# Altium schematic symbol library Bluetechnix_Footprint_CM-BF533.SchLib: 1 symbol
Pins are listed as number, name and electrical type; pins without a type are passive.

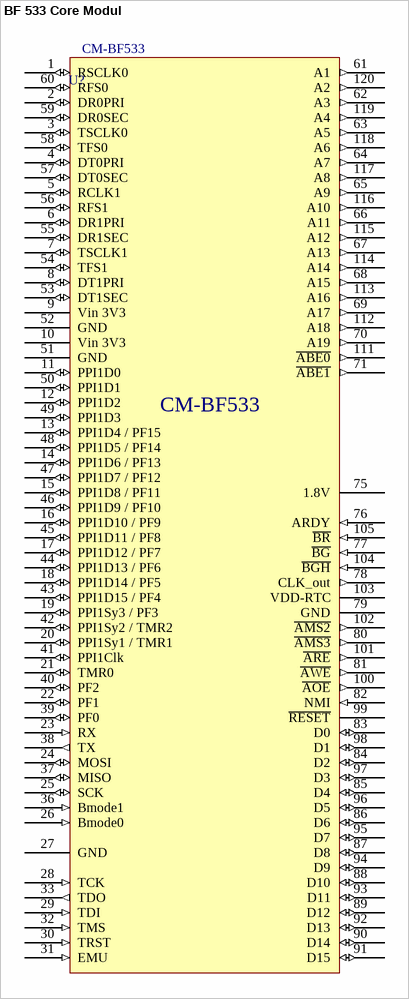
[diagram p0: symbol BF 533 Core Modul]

## BF 533 Core Modul
designator U?, comment CM-BF533
DSP Balckfin 533
pins: 1 RSCLK0 (io), 2 DR0PRI (io), 3 TSCLK0 (io), 4 DT0PRI (io), 5 RCLK1 (io), 6 DR1PRI (io), 7 TSCLK1 (io), 8 DT1PRI (io), 9 Vin 3V3 (power), 10 Vin 3V3 (power), 11 PPI1D0 (io), 12 PPI1D2 (io), 13 PPI1D4 / PF15 (io), 14 PPI1D6 / PF13 (io), 15 PPI1D8 / PF11 (io), 16 PPI1D10 / PF9 (io), 17 PPI1D12 / PF7 (io), 18 PPI1D14 / PF5 (io), 19 PPI1Sy3 / PF3 (io), 20 PPI1Sy1 / TMR1 (io), 21 TMR0 (io), 22 PF1 (io), 23 RX (in), 24 MOSI (io), 25 SCK (io), 26 Bmode0 (in), 27 GND (power), 28 TCK (in), 29 TDI (in), 30 TRST (in), 31 EMU (in), 32 TMS (in), 33 TDO (out), 36 Bmode1 (in), 37 MISO (io), 38 TX (out), 39 PF0 (io), 40 PF2 (io), 41 PPI1Clk (io), 42 PPI1Sy2 / TMR2 (io), 43 PPI1D15 / PF4 (io), 44 PPI1D13 / PF6 (io), 45 PPI1D11 / PF8 (io), 46 PPI1D9 / PF10 (io), 47 PPI1D7 / PF12 (io), 48 PPI1D5 / PF14 (io), 49 PPI1D3 (io), 50 PPI1D1 (io), 51 GND (power), 52 GND (power), 53 DT1SEC (io), 54 TFS1 (io), 55 DR1SEC (io), 56 RFS1 (io), 57 DT0SEC (io), 58 TFS0 (io), 59 DR0SEC (io), 60 RFS0 (io), 61 A1 (out), 62 A3 (out), 63 A5 (out), 64 A7 (out), 65 A9 (out), 66 A11 (out), 67 A13 (out), 68 A15 (out), 69 A17 (out), 70 A19 (out), 71 ~{ABE1} (out), 75 1.8V (power), 76 ARDY (in), 77 ~{BG} (in), 78 CLK_out (out), 79 GND (power), 80 ~{AMS3} (out), 81 ~{AWE} (out), 82 NMI (in), 83 D0 (io), 84 D2 (io), 85 D4 (io), 86 D6 (io), 87 D8 (io), 88 D10 (io), 89 D12 (io), 90 D14 (io), 91 D15 (io), 92 D13 (io), 93 D11 (io), 94 D9 (io), 95 D7 (io), 96 D5 (io), 97 D3 (io), 98 D1 (io), 99 ~{RESET}, 100 ~{AOE} (out), 101 ~{ARE} (out), 102 ~{AMS2} (out), 103 VDD-RTC (power), 104 ~{BGH} (in), 105 ~{BR} (in), 111 ~{ABE0} (out), 112 A18 (out), 113 A16 (out), 114 A14 (out), 115 A12 (out), 116 A10 (out), 117 A8 (out), 118 A6 (out), 119 A4 (out), 120 A2 (out)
